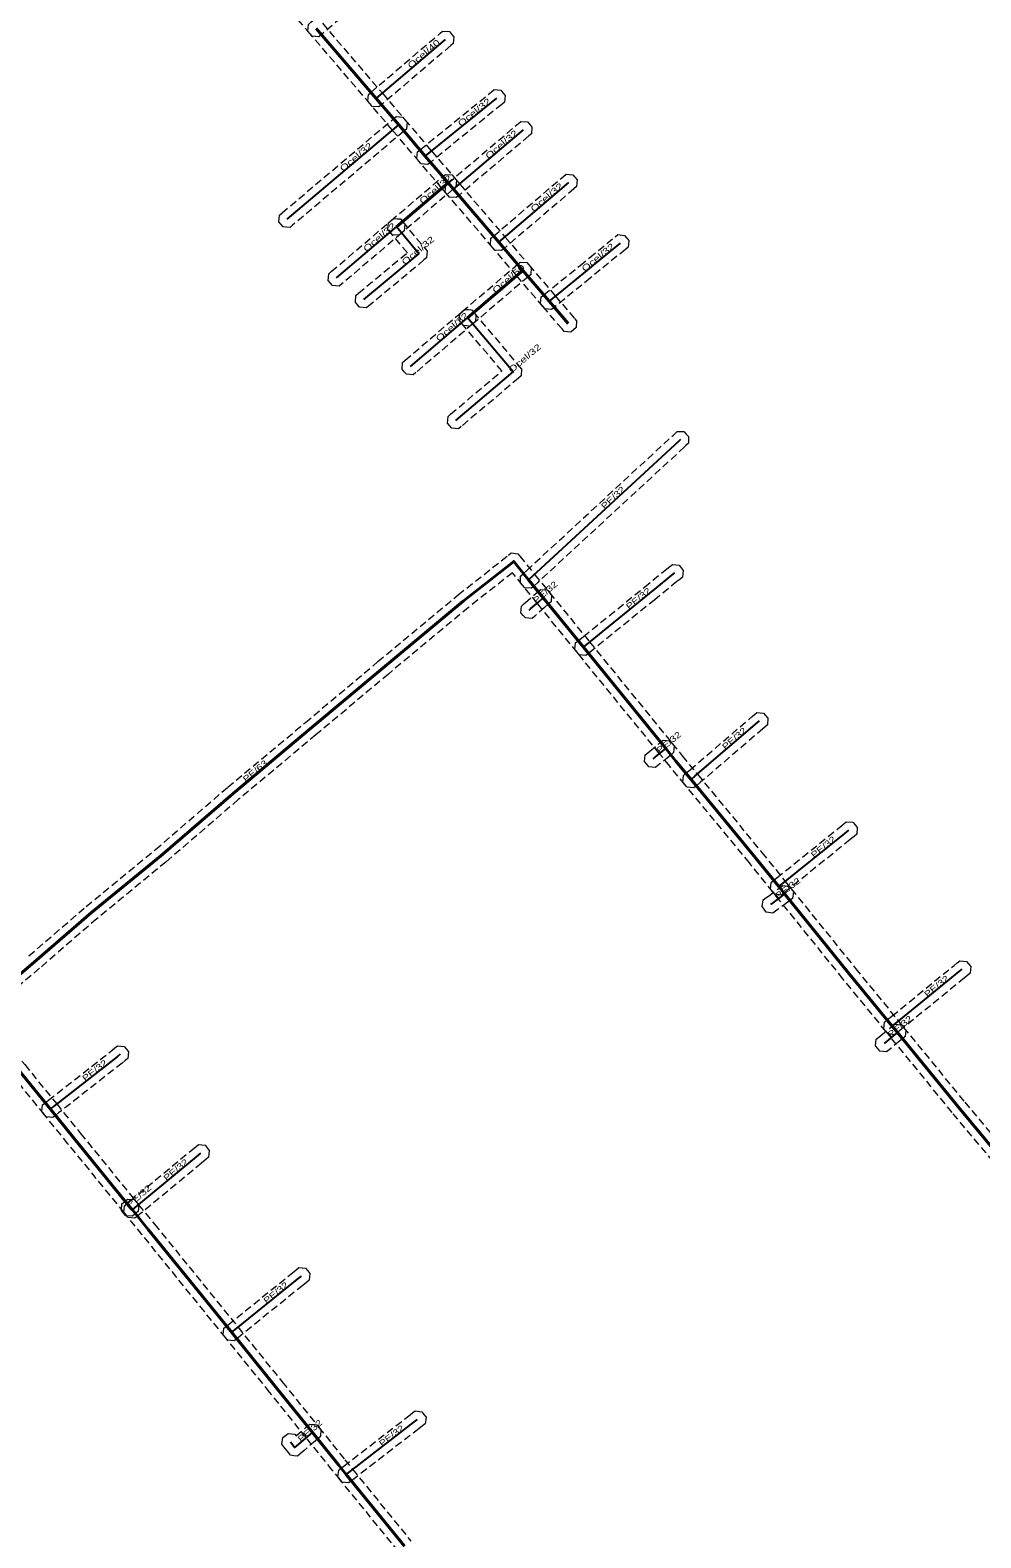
# Model space of a CAD drawing. Extents: x -588392 to -586332, y -1208963 to -1206334.
# Drawn here: x -588243.8 to -588126.9, y -1206733.6 to -1206548.1 of the extents above; entities that cross this region are included whole.
import ezdxf

# ---------------------------------------------------------------- set-up
doc = ezdxf.new("R2010")
doc.units = 0
doc.header["$LTSCALE"] = 0.3
doc.linetypes.add('MEDIUM_DASHED', pattern=[4.5, 3, -1.5])
for name, color, linetype, lineweight in [('1', 7, 'MEDIUM_DASHED', 13), ('14', 7, 'Continuous', 25), ('24', 7, 'Continuous', 25)]:
    doc.layers.add(name, color=color, linetype=linetype, lineweight=lineweight)
doc.layers.add('20', color=7, linetype='Continuous')
doc.layers.add('30', color=7, linetype='Continuous')

msp = doc.modelspace()

# ---------------------------------------------------------------- linework, layer by layer
at = {"layer": '1'}
for points in [[(-588209.624, -1206547.428), (-588209.309, -1206547.159), (-588200.789, -1206539.889), (-588200.474, -1206539.62), (-588199.648, -1206539.686), (-588199.379, -1206540.001), (-588199.11, -1206540.316), (-588199.176, -1206541.142), (-588199.491, -1206541.411), (-588208.011, -1206548.681), (-588208.326, -1206548.95), (-588209.152, -1206548.884), (-588209.421, -1206548.569), (-588209.69, -1206548.254)], [(-588202.245, -1206556.059), (-588201.93, -1206555.79), (-588193.42, -1206548.52), (-588193.105, -1206548.251), (-588192.279, -1206548.315), (-588192.01, -1206548.63), (-588191.741, -1206548.945), (-588191.805, -1206549.771), (-588192.12, -1206550.04), (-588200.63, -1206557.31), (-588200.945, -1206557.579), (-588201.771, -1206557.515), (-588202.04, -1206557.2), (-588202.309, -1206556.885)], [(-588196.202, -1206563.115), (-588195.88, -1206562.854), (-588187.09, -1206555.714), (-588186.769, -1206555.453), (-588185.945, -1206555.538), (-588185.684, -1206555.86), (-588185.423, -1206556.181), (-588185.508, -1206557.005), (-588185.83, -1206557.266), (-588194.62, -1206564.406), (-588194.941, -1206564.667), (-588195.765, -1206564.582), (-588196.026, -1206564.26), (-588196.287, -1206563.939)], [(-588213.172, -1206570.884), (-588212.856, -1206570.616), (-588199.156, -1206559.036), (-588198.84, -1206558.769), (-588198.014, -1206558.838), (-588197.746, -1206559.154), (-588197.479, -1206559.47), (-588197.548, -1206560.296), (-588197.864, -1206560.564), (-588211.564, -1206572.144), (-588211.88, -1206572.411), (-588212.706, -1206572.342), (-588212.974, -1206572.026), (-588213.241, -1206571.71)], [(-588192.733, -1206567.216), (-588192.417, -1206566.948), (-588183.797, -1206559.628), (-588183.481, -1206559.36), (-588182.656, -1206559.427), (-588182.388, -1206559.743), (-588182.12, -1206560.059), (-588182.187, -1206560.884), (-588182.503, -1206561.152), (-588191.123, -1206568.472), (-588191.439, -1206568.74), (-588192.264, -1206568.673), (-588192.532, -1206568.357), (-588192.8, -1206568.041)], [(-588199.764, -1206571.838), (-588199.449, -1206571.569), (-588193.089, -1206566.149), (-588192.774, -1206565.88), (-588191.948, -1206565.946), (-588191.679, -1206566.261), (-588191.41, -1206566.576), (-588191.476, -1206567.402), (-588191.791, -1206567.671), (-588198.151, -1206573.091), (-588198.466, -1206573.36), (-588199.292, -1206573.294), (-588199.561, -1206572.979), (-588199.83, -1206572.664)], [(-588187.164, -1206573.738), (-588186.849, -1206573.469), (-588178.249, -1206566.129), (-588177.934, -1206565.86), (-588177.108, -1206565.926), (-588176.839, -1206566.241), (-588176.57, -1206566.556), (-588176.636, -1206567.382), (-588176.951, -1206567.651), (-588185.551, -1206574.991), (-588185.866, -1206575.26), (-588186.692, -1206575.194), (-588186.961, -1206574.879), (-588187.23, -1206574.564)], [(-588207.114, -1206578.108), (-588206.799, -1206577.839), (-588199.449, -1206571.569), (-588199.134, -1206571.3), (-588198.308, -1206571.366), (-588198.039, -1206571.681), (-588197.77, -1206571.996), (-588197.836, -1206572.822), (-588198.151, -1206573.091), (-588205.501, -1206579.361), (-588205.816, -1206579.63), (-588206.642, -1206579.564), (-588206.911, -1206579.249), (-588207.18, -1206578.934)], [(-588203.768, -1206580.766), (-588203.449, -1206580.501), (-588197.449, -1206575.511), (-588199.568, -1206572.97), (-588199.833, -1206572.652), (-588199.758, -1206571.827), (-588199.44, -1206571.562), (-588199.122, -1206571.297), (-588198.297, -1206571.372), (-588198.032, -1206571.69), (-588195.272, -1206575), (-588195.006, -1206575.318), (-588195.044, -1206575.731), (-588195.082, -1206576.144), (-588195.401, -1206576.409), (-588202.171, -1206582.039), (-588202.489, -1206582.304), (-588203.314, -1206582.228), (-588203.579, -1206581.909), (-588203.844, -1206581.591)], [(-588170.307, -1206574.843), (-588170.628, -1206575.105), (-588173.727, -1206577.634), (-588174.948, -1206578.635), (-588179.389, -1206582.246), (-588179.71, -1206582.507), (-588180.535, -1206582.422), (-588180.796, -1206582.101), (-588181.057, -1206581.78), (-588180.972, -1206580.955), (-588180.651, -1206580.694), (-588176.212, -1206577.085), (-588174.993, -1206576.086), (-588171.892, -1206573.555), (-588171.571, -1206573.293), (-588170.747, -1206573.377), (-588170.485, -1206573.698), (-588170.223, -1206574.019)], [(-588191.004, -1206583.018), (-588190.689, -1206582.749), (-588183.879, -1206576.939), (-588183.564, -1206576.67), (-588182.738, -1206576.736), (-588182.469, -1206577.051), (-588182.2, -1206577.366), (-588182.266, -1206578.192), (-588182.581, -1206578.461), (-588189.391, -1206584.271), (-588189.706, -1206584.54), (-588190.532, -1206584.474), (-588190.801, -1206584.159), (-588191.07, -1206583.844)], [(-588198.024, -1206589.008), (-588197.709, -1206588.739), (-588190.689, -1206582.749), (-588190.374, -1206582.48), (-588189.548, -1206582.546), (-588189.279, -1206582.861), (-588189.01, -1206583.176), (-588189.076, -1206584.002), (-588189.391, -1206584.271), (-588196.411, -1206590.261), (-588196.726, -1206590.53), (-588197.552, -1206590.464), (-588197.821, -1206590.149), (-588198.09, -1206589.834)], [(-588192.441, -1206595.643), (-588192.125, -1206595.376), (-588185.828, -1206590.06), (-588190.805, -1206584.154), (-588191.072, -1206583.838), (-588191.001, -1206583.012), (-588190.684, -1206582.745), (-588190.368, -1206582.478), (-588189.542, -1206582.549), (-588189.275, -1206582.866), (-588183.655, -1206589.536), (-588183.389, -1206589.853), (-588183.459, -1206590.677), (-588183.775, -1206590.944), (-588190.835, -1206596.904), (-588191.151, -1206597.171), (-588191.977, -1206597.101), (-588192.244, -1206596.785), (-588192.511, -1206596.469)], [(-588162.882, -1206598.952), (-588163.183, -1206599.237), (-588163.367, -1206599.411), (-588181.402, -1206616.065), (-588181.856, -1206616.484), (-588182.16, -1206616.765), (-588182.988, -1206616.731), (-588183.269, -1206616.427), (-588183.55, -1206616.123), (-588183.516, -1206615.295), (-588183.212, -1206615.014), (-588182.758, -1206614.595), (-588164.733, -1206597.949), (-588164.557, -1206597.783), (-588164.256, -1206597.498), (-588163.428, -1206597.522), (-588163.143, -1206597.823), (-588162.858, -1206598.124)], [(-588176.75, -1206623.509), (-588176.427, -1206623.25), (-588175.768, -1206622.722), (-588168.292, -1206616.645), (-588165.532, -1206614.387), (-588165.171, -1206614.108), (-588164.843, -1206613.855), (-588164.021, -1206613.961), (-588163.768, -1206614.289), (-588163.515, -1206614.617), (-588163.621, -1206615.439), (-588163.949, -1206615.692), (-588164.288, -1206615.953), (-588167.028, -1206618.195), (-588174.512, -1206624.278), (-588175.175, -1206624.81), (-588175.499, -1206625.069), (-588176.322, -1206624.979), (-588176.581, -1206624.656), (-588176.84, -1206624.332)], [(-588183.426, -1206619.001), (-588183.117, -1206618.725), (-588182.921, -1206618.549), (-588181.877, -1206617.646), (-588181.389, -1206617.217), (-588181.078, -1206616.944), (-588180.25, -1206616.998), (-588179.977, -1206617.309), (-588179.704, -1206617.62), (-588179.758, -1206618.448), (-588180.069, -1206618.721), (-588180.563, -1206619.154), (-588181.599, -1206620.051), (-588181.783, -1206620.215), (-588182.092, -1206620.491), (-588182.919, -1206620.446), (-588183.195, -1206620.137), (-588183.471, -1206619.828)], [(-588163.501, -1206639.816), (-588163.185, -1206639.548), (-588162.679, -1206639.119), (-588155.024, -1206632.553), (-588154.796, -1206632.355), (-588154.484, -1206632.083), (-588153.657, -1206632.141), (-588153.385, -1206632.454), (-588153.113, -1206632.766), (-588153.171, -1206633.593), (-588153.484, -1206633.865), (-588153.716, -1206634.067), (-588161.381, -1206640.641), (-588161.893, -1206641.074), (-588162.209, -1206641.342), (-588163.034, -1206641.273), (-588163.302, -1206640.957), (-588163.57, -1206640.641)], [(-588168.184, -1206637.278), (-588167.863, -1206637.016), (-588167.642, -1206636.835), (-588166.525, -1206635.928), (-588166.297, -1206635.738), (-588165.978, -1206635.473), (-588165.154, -1206635.548), (-588164.889, -1206635.866), (-588164.624, -1206636.185), (-588164.699, -1206637.009), (-588165.017, -1206637.274), (-588165.255, -1206637.472), (-588166.378, -1206638.385), (-588166.597, -1206638.564), (-588166.918, -1206638.826), (-588167.742, -1206638.744), (-588168.004, -1206638.423), (-588168.266, -1206638.102)], [(-588152.689, -1206652.972), (-588152.367, -1206652.711), (-588151.999, -1206652.412), (-588144.254, -1206646.167), (-588143.78, -1206645.772), (-588143.462, -1206645.507), (-588142.637, -1206645.582), (-588142.372, -1206645.9), (-588142.107, -1206646.218), (-588142.182, -1206647.043), (-588142.5, -1206647.308), (-588142.986, -1206647.713), (-588150.741, -1206653.968), (-588151.109, -1206654.265), (-588151.431, -1206654.526), (-588152.254, -1206654.439), (-588152.515, -1206654.117), (-588152.776, -1206653.795)], [(-588153.675, -1206655.129), (-588153.341, -1206654.884), (-588153.043, -1206654.665), (-588151.852, -1206653.784), (-588151.59, -1206653.593), (-588151.256, -1206653.349), (-588150.437, -1206653.477), (-588150.193, -1206653.812), (-588149.949, -1206654.146), (-588150.077, -1206654.965), (-588150.412, -1206655.209), (-588150.668, -1206655.396), (-588151.857, -1206656.275), (-588152.159, -1206656.496), (-588152.493, -1206656.741), (-588153.311, -1206656.615), (-588153.556, -1206656.281), (-588153.801, -1206655.947)], [(-588138.758, -1206670.148), (-588138.435, -1206669.889), (-588137.829, -1206669.403), (-588130.202, -1206663.175), (-588129.822, -1206662.865), (-588129.501, -1206662.603), (-588128.677, -1206662.687), (-588128.415, -1206663.008), (-588128.153, -1206663.329), (-588128.237, -1206664.153), (-588128.558, -1206664.415), (-588128.938, -1206664.725), (-588136.571, -1206670.957), (-588137.183, -1206671.449), (-588137.506, -1206671.708), (-588138.33, -1206671.618), (-588138.589, -1206671.295), (-588138.848, -1206670.972)], [(-588136.226, -1206671.947), (-588136.546, -1206672.21), (-588136.864, -1206672.472), (-588137.94, -1206673.357), (-588138.195, -1206673.561), (-588138.519, -1206673.82), (-588139.342, -1206673.729), (-588139.601, -1206673.405), (-588139.86, -1206673.081), (-588139.769, -1206672.258), (-588139.445, -1206671.999), (-588139.2, -1206671.803), (-588138.136, -1206670.928), (-588137.818, -1206670.666), (-588137.498, -1206670.403), (-588136.673, -1206670.482), (-588136.41, -1206670.802), (-588136.147, -1206671.122)], [(-588231.83, -1206674.639), (-588232.153, -1206674.899), (-588232.518, -1206675.193), (-588240.35, -1206681.335), (-588240.734, -1206681.64), (-588241.058, -1206681.898), (-588241.881, -1206681.803), (-588242.139, -1206681.479), (-588242.397, -1206681.155), (-588242.302, -1206680.332), (-588241.978, -1206680.074), (-588241.59, -1206679.765), (-588233.762, -1206673.627), (-588233.407, -1206673.341), (-588233.085, -1206673.081), (-588232.261, -1206673.17), (-588232.001, -1206673.493), (-588231.741, -1206673.815)], [(-588232.229, -1206692.748), (-588231.91, -1206692.483), (-588231.569, -1206692.201), (-588224.037, -1206685.949), (-588223.475, -1206685.487), (-588223.155, -1206685.224), (-588222.33, -1206685.305), (-588222.067, -1206685.625), (-588221.804, -1206685.945), (-588221.885, -1206686.77), (-588222.205, -1206687.033), (-588222.763, -1206687.491), (-588230.291, -1206693.739), (-588230.632, -1206694.023), (-588230.951, -1206694.287), (-588231.776, -1206694.211), (-588232.041, -1206693.892), (-588232.305, -1206693.573)], [(-588232.562, -1206692.524), (-588232.248, -1206692.254), (-588232.171, -1206692.188), (-588231.857, -1206691.918), (-588231.031, -1206691.982), (-588230.761, -1206692.296), (-588230.491, -1206692.61), (-588230.555, -1206693.436), (-588230.869, -1206693.706), (-588230.946, -1206693.772), (-588231.26, -1206694.042), (-588232.086, -1206693.978), (-588232.356, -1206693.664), (-588232.626, -1206693.35)], [(-588220, -1206707.804), (-588219.677, -1206707.544), (-588219.488, -1206707.392), (-588211.568, -1206700.982), (-588211.107, -1206700.611), (-588210.784, -1206700.351), (-588209.961, -1206700.44), (-588209.701, -1206700.763), (-588209.441, -1206701.086), (-588209.53, -1206701.909), (-588209.853, -1206702.169), (-588210.312, -1206702.538), (-588218.232, -1206708.948), (-588218.423, -1206709.102), (-588218.746, -1206709.362), (-588219.569, -1206709.273), (-588219.829, -1206708.95), (-588220.089, -1206708.627)], [(-588205.892, -1206725.257), (-588205.564, -1206725.004), (-588205.271, -1206724.778), (-588197.264, -1206718.6), (-588196.806, -1206718.242), (-588196.48, -1206717.987), (-588195.658, -1206718.088), (-588195.402, -1206718.414), (-588195.147, -1206718.74), (-588195.248, -1206719.562), (-588195.574, -1206719.818), (-588196.036, -1206720.18), (-588204.049, -1206726.362), (-588204.342, -1206726.588), (-588204.67, -1206726.841), (-588205.492, -1206726.735), (-588205.745, -1206726.407), (-588205.998, -1206726.079)], [(-588211.291, -1206720.861), (-588211.137, -1206721.061), (-588210.06, -1206720.14), (-588209.758, -1206719.882), (-588209.443, -1206719.613), (-588208.617, -1206719.679), (-588208.348, -1206719.994), (-588208.079, -1206720.309), (-588208.145, -1206721.135), (-588208.46, -1206721.404), (-588208.76, -1206721.66), (-588210.143, -1206722.843), (-588210.647, -1206723.266), (-588210.973, -1206723.54), (-588211.397, -1206723.494), (-588211.821, -1206723.448), (-588212.082, -1206723.111), (-588212.622, -1206722.411), (-588212.875, -1206722.083), (-588212.769, -1206721.261), (-588212.441, -1206721.008), (-588212.113, -1206720.755)]]:
    msp.add_lwpolyline(points, close=True, dxfattribs=at)
for points in [[(-588207.9, -1206547.27), (-588200.519, -1206555.901), (-588197.749, -1206559.152), (-588194.49, -1206562.981), (-588191.677, -1206566.264), (-588191.006, -1206567.064), (-588185.44, -1206573.58), (-588182.469, -1206577.051), (-588179.259, -1206580.822), (-588176.899, -1206583.591), (-588176.63, -1206583.907), (-588176.696, -1206584.733), (-588177.011, -1206585.001), (-588177.327, -1206585.27), (-588178.153, -1206585.204), (-588178.421, -1206584.889), (-588180.781, -1206582.118), (-588183.991, -1206578.349), (-588186.96, -1206574.88), (-588192.534, -1206568.356), (-588193.203, -1206567.556), (-588196.01, -1206564.279), (-588199.271, -1206560.448), (-588202.041, -1206557.199), (-588209.42, -1206548.57), (-588215.201, -1206541.799)], [(-588243.99, -1206662.02), (-588236.934, -1206655.925), (-588228.424, -1206648.935), (-588219.537, -1206641.267), (-588209.982, -1206633.293), (-588201.061, -1206625.813), (-588191.2, -1206617.593), (-588184.988, -1206612.704), (-588184.666, -1206612.451), (-588183.852, -1206612.541), (-588183.594, -1206612.859), (-588181.758, -1206615.118), (-588179.953, -1206617.338), (-588175.025, -1206623.399), (-588164.881, -1206635.875)], [(-588125.407, -1206687.292), (-588130.441, -1206681.277), (-588137.957, -1206672.07), (-588138.584, -1206671.301), (-588143.866, -1206664.83), (-588151.779, -1206655.029), (-588152.516, -1206654.116), (-588155.385, -1206650.562), (-588163.311, -1206640.947), (-588165.184, -1206638.673), (-588166.433, -1206637.137), (-588176.577, -1206624.661), (-588181.505, -1206618.6), (-588183.31, -1206616.38), (-588184.525, -1206614.885), (-588189.94, -1206619.147), (-588199.779, -1206627.347), (-588208.698, -1206634.827), (-588218.243, -1206642.793), (-588227.136, -1206650.465), (-588235.646, -1206657.455), (-588242.69, -1206663.54), (-588249.533, -1206669.348)], [(-588164.881, -1206635.875), (-588163.636, -1206637.407), (-588161.767, -1206639.675), (-588153.835, -1206649.298), (-588150.96, -1206652.86), (-588150.223, -1206653.773), (-588142.314, -1206663.57), (-588137.034, -1206670.037), (-588136.407, -1206670.806), (-588128.899, -1206680.003), (-588123.873, -1206686.008)], [(-588249.533, -1206669.348), (-588249.588, -1206669.388), (-588248.516, -1206670.652), (-588246.605, -1206672.908), (-588244.5, -1206675.392), (-588240.579, -1206680.227), (-588237.634, -1206683.859), (-588230.745, -1206692.316), (-588230.496, -1206692.622), (-588228.534, -1206695.029), (-588220.863, -1206704.491), (-588218.272, -1206707.694), (-588212.832, -1206714.422), (-588208.33, -1206720.016), (-588205.122, -1206724.001), (-588204.177, -1206725.166), (-588197.003, -1206734)], [(-588198.557, -1206735.26), (-588205.729, -1206726.426), (-588206.678, -1206725.259), (-588209.888, -1206721.27), (-588214.388, -1206715.678), (-588219.828, -1206708.952), (-588222.417, -1206705.749), (-588230.086, -1206696.291), (-588232.046, -1206693.884), (-588232.295, -1206693.578), (-588239.186, -1206685.121), (-588242.133, -1206681.487), (-588246.04, -1206676.668)]]:
    msp.add_lwpolyline(points, dxfattribs=at)
at = {"layer": '14'}
for p, q in [((-588201.28, -1206556.55), (-588192.77, -1206549.28)), ((-588195.25, -1206563.63), (-588186.46, -1206556.49)), ((-588212.21, -1206571.38), (-588198.51, -1206559.8)), ((-588191.77, -1206567.71), (-588183.15, -1206560.39)), ((-588186.2, -1206574.23), (-588177.6, -1206566.89)), ((-588206.15, -1206578.6), (-588198.8, -1206572.33)), ((-588197.06, -1206589.5), (-588190.04, -1206583.51))]:
    msp.add_line(p, q, dxfattribs=at)
at = {"layer": '14', "lineweight": 40}
for p, q in [((-588198.8, -1206572.33), (-588192.44, -1206566.91)), ((-588190.04, -1206583.51), (-588183.23, -1206577.7))]:
    msp.add_line(p, q, dxfattribs=at)
msp.add_lwpolyline([(-588177.66, -1206584.24), (-588180.02, -1206581.47), (-588183.23, -1206577.7), (-588186.2, -1206574.23), (-588191.77, -1206567.71), (-588192.44, -1206566.91), (-588195.25, -1206563.63), (-588198.51, -1206559.8), (-588201.28, -1206556.55), (-588208.66, -1206547.92)], dxfattribs=at)
at = {"layer": '14'}
for points in [[(-588202.81, -1206581.27), (-588196.04, -1206575.64), (-588198.8, -1206572.33)], [(-588171.26, -1206574.33), (-588174.36, -1206576.86), (-588175.58, -1206577.86), (-588180.02, -1206581.47)], [(-588191.48, -1206596.14), (-588184.42, -1206590.18), (-588190.04, -1206583.51)]]:
    msp.add_lwpolyline(points, dxfattribs=at)
at = {"layer": '24'}
msp.add_line((-588231.597, -1206693.013), (-588231.52, -1206692.947), dxfattribs=at)
for points in [[(-588163.87, -1206598.51), (-588164.05, -1206598.68), (-588182.08, -1206615.33), (-588182.534, -1206615.749)], [(-588175.801, -1206624.03), (-588175.14, -1206623.5), (-588167.66, -1206617.42), (-588167.021, -1206616.897), (-588164.91, -1206615.17), (-588164.56, -1206614.9)], [(-588182.45, -1206619.47), (-588182.26, -1206619.3), (-588181.768, -1206618.874), (-588181.22, -1206618.4), (-588180.729, -1206617.969)], [(-588162.539, -1206640.311), (-588162.03, -1206639.88), (-588154.37, -1206633.31), (-588154.14, -1206633.11)], [(-588167.23, -1206637.79), (-588167.01, -1206637.61), (-588166.661, -1206637.326), (-588165.89, -1206636.7), (-588165.657, -1206636.506)], [(-588151.738, -1206653.488), (-588151.37, -1206653.19), (-588143.62, -1206646.94), (-588143.14, -1206646.54)], [(-588152.75, -1206655.69), (-588152.45, -1206655.47), (-588151.964, -1206655.111), (-588151.26, -1206654.59), (-588151.001, -1206654.401)], [(-588137.809, -1206670.669), (-588137.2, -1206670.18), (-588129.57, -1206663.95), (-588129.19, -1206663.64)], [(-588137.182, -1206671.438), (-588137.5, -1206671.7), (-588138.256, -1206672.322), (-588138.57, -1206672.58), (-588138.82, -1206672.78)], [(-588232.78, -1206674.12), (-588233.14, -1206674.41), (-588240.97, -1206680.55), (-588241.356, -1206680.857)], [(-588231.271, -1206693.253), (-588230.93, -1206692.97), (-588223.4, -1206686.72), (-588222.84, -1206686.26)], [(-588219.05, -1206708.323), (-588218.86, -1206708.17), (-588210.94, -1206701.76), (-588210.48, -1206701.39)], [(-588204.953, -1206725.796), (-588204.66, -1206725.57), (-588196.65, -1206719.39), (-588196.19, -1206719.03)], [(-588211.83, -1206721.8), (-588211.29, -1206722.5), (-588210.79, -1206722.08), (-588210.173, -1206721.552), (-588209.41, -1206720.9), (-588209.109, -1206720.643)]]:
    msp.add_lwpolyline(points, dxfattribs=at)
at = {"layer": '24', "lineweight": 40}
for points in [[(-588250.15, -1206668.56), (-588243.34, -1206662.78), (-588236.29, -1206656.69), (-588227.78, -1206649.7), (-588218.89, -1206642.03), (-588209.34, -1206634.06), (-588200.42, -1206626.58), (-588190.57, -1206618.37), (-588184.37, -1206613.49), (-588182.534, -1206615.749), (-588180.729, -1206617.969), (-588175.801, -1206624.03), (-588165.657, -1206636.506), (-588164.41, -1206638.04), (-588162.539, -1206640.311), (-588154.61, -1206649.93), (-588151.738, -1206653.488), (-588151.001, -1206654.401), (-588143.09, -1206664.2), (-588137.809, -1206670.669), (-588137.182, -1206671.438), (-588129.67, -1206680.64), (-588124.64, -1206686.65)], [(-588197.78, -1206734.63), (-588204.953, -1206725.796), (-588205.9, -1206724.63), (-588209.109, -1206720.643), (-588213.61, -1206715.05), (-588219.05, -1206708.323), (-588221.64, -1206705.12), (-588229.31, -1206695.66), (-588231.271, -1206693.253), (-588231.52, -1206692.947), (-588238.41, -1206684.49), (-588241.356, -1206680.857), (-588245.27, -1206676.03)]]:
    msp.add_lwpolyline(points, dxfattribs=at)

# ---------------------------------------------------------------- texts
at = {"layer": '20', "width": 1.4}
for s, rotation, p in [('Ocel/40', 40.507, (-588197.025, -1206552.915)), ('Ocel/32', 39.086, (-588190.855, -1206560.06)), ('Ocel/32', 40.338, (-588187.46, -1206564.05)), ('Ocel/32', 40.206, (-588205.36, -1206565.59)), ('Ocel/32', 40.438, (-588195.582, -1206569.587)), ('Ocel/32', 40.48, (-588181.9, -1206570.56)), ('Ocel/32', 40.466, (-588202.475, -1206575.465)), ('Ocel/32', 39.747, (-588197.768, -1206577.077)), ('Ocel/32', 39.113, (-588175.636, -1206577.905)), ('Ocel/50', 40.469, (-588186.597, -1206580.572)), ('Ocel/32', 40.473, (-588193.55, -1206586.505)), ('Ocel/32', 40.171, (-588184.618, -1206590.347))]:
    msp.add_text(s, height=0.75, rotation=rotation, dxfattribs=at).set_placement(p)
at = {"layer": '30', "width": 1.3}
for s, rotation, p in [('PE/32', 42.721, (-588173.201, -1206607.13)), ('PE/32', 40.859, (-588181.59, -1206618.719)), ('PE/32', 39.105, (-588170.179, -1206619.467)), ('PE/32', 39.074, (-588166.443, -1206637.149)), ('PE/32', 40.62, (-588158.338, -1206636.713)), ('PE/63', 39.847, (-588217.289, -1206640.694)), ('PE/32', 38.884, (-588147.436, -1206650.017)), ('PE/32', 36.504, (-588151.876, -1206655.045)), ('PE/32', 39.232, (-588133.498, -1206667.157)), ('PE/32', 39.446, (-588138, -1206672.111)), ('PE/32', 38.102, (-588237.067, -1206677.489)), ('PE/32', 39.693, (-588227.057, -1206689.755)), ('PE/32', 40.601, (-588231.559, -1206692.98)), ('PE/32', 38.985, (-588214.766, -1206704.856)), ('PE/32', 40.555, (-588210.534, -1206721.861)), ('PE/32', 37.651, (-588200.57, -1206722.414))]:
    msp.add_text(s, height=0.75, rotation=rotation, dxfattribs=at).set_placement(p)

doc.saveas('drawing.dxf')
